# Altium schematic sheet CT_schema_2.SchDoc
size 454 x 387 mm
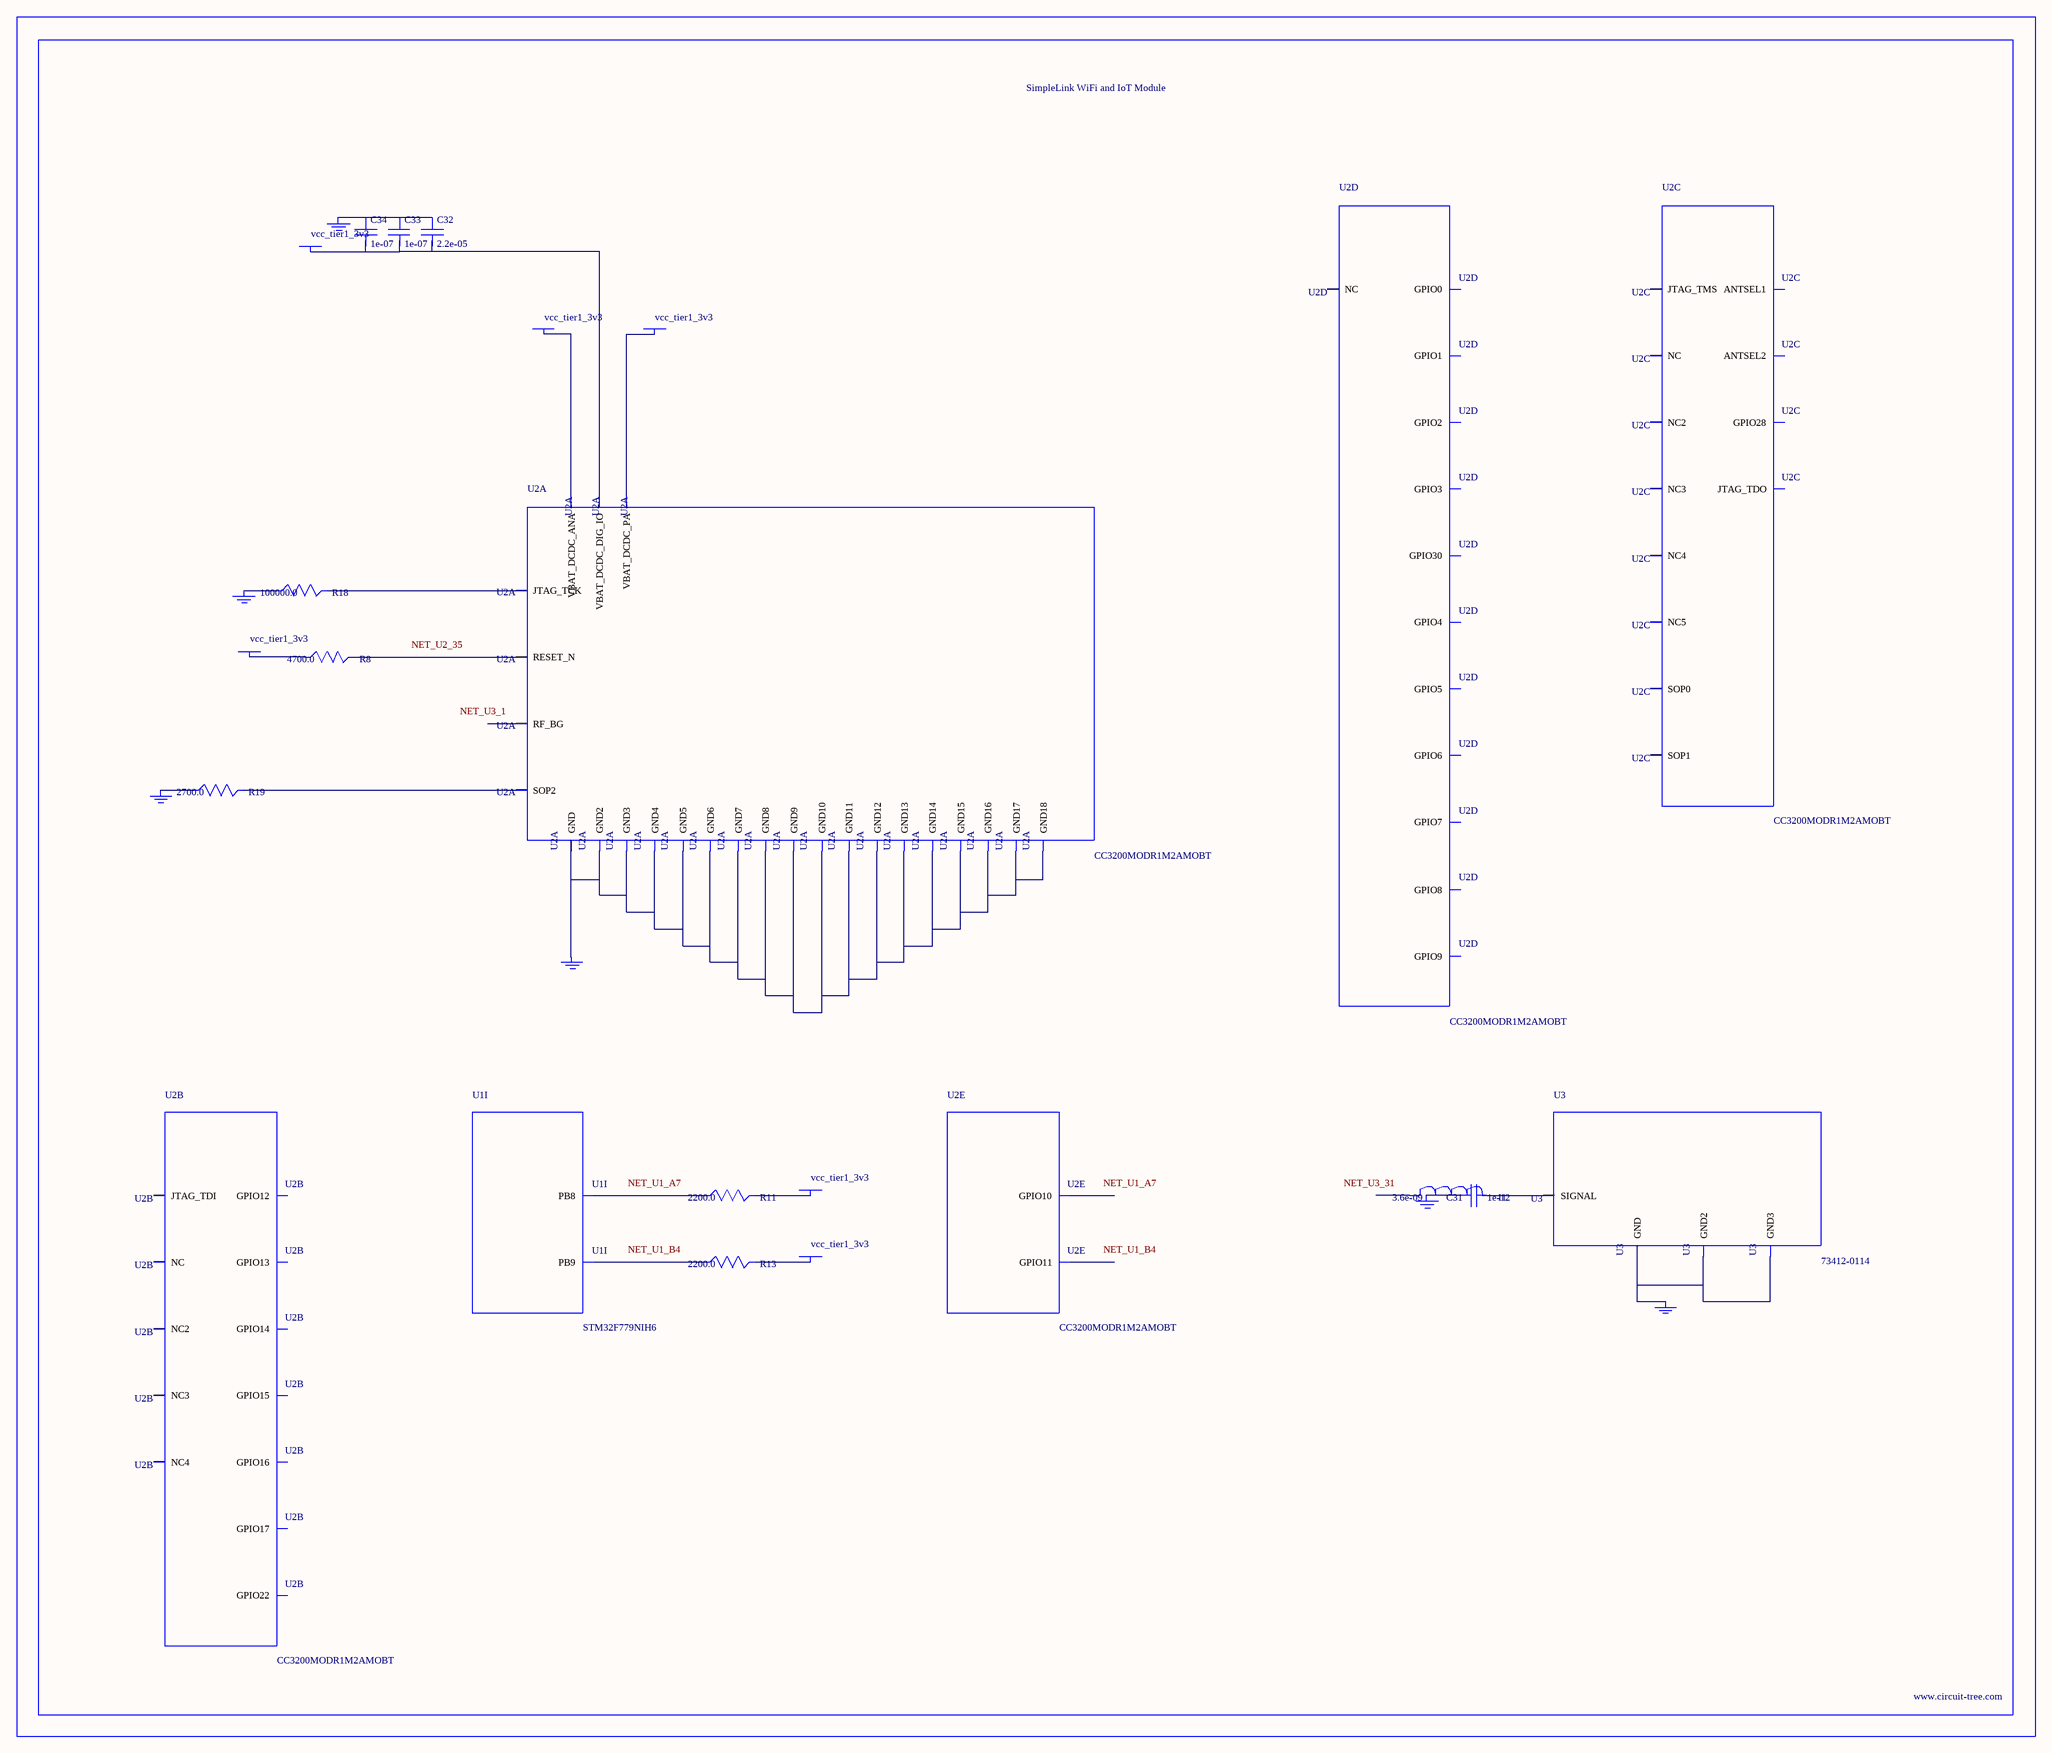
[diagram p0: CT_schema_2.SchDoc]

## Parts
BORDER1  (no value)
C31  1e-12  [C0402]
C32  2.2e-05  [C1210]
C33  1e-07  [C0402]
C34  1e-07  [C0402]
GND_INSTANCE_1_0  (no value)
GND_INSTANCE_1_1  (no value)
GND_INSTANCE_1_2  (no value)
GND_INSTANCE_1_3  (no value)
GND_INSTANCE_1_4  (no value)
GND_INSTANCE_1_5  (no value)
I1  3.6e-09  [C0402]
POWER_INSTANCE_1_0  vcc_tier1_3v3
POWER_INSTANCE_1_1  vcc_tier1_3v3
POWER_INSTANCE_1_2  vcc_tier1_3v3
POWER_INSTANCE_1_3  vcc_tier1_3v3
POWER_INSTANCE_1_4  vcc_tier1_3v3
POWER_INSTANCE_1_5  vcc_tier1_3v3
R8  4700.0  [R0603]
R11  2200.0  [R0603]
R13  2200.0  [R0603]
R18  100000.0  [R0603]
R19  2700.0  [R0603]
U1  STM32F779NIH6  [TFBGA216]  (part I of 16)
U2  CC3200MODR1M2AMOBT  [LGA63S127P16X13_2050X1750X150]  (parts A,B,C,D,E of 5)
U3  73412-0114  [COAXIAL_C]

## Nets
NetC31_1: C31.1 I1.2 U3.1(SIGNAL)
NetC31_2: C31.2 GND_INSTANCE_1_4.0(GND)
NetC32_1: C32.1 C33.1 C34.1 GND_INSTANCE_1_2.0(GND)
NetC32_2: C32.2 C33.2 C34.2 POWER_INSTANCE_1_2.0(PWR) U2.40(VBAT_DCDC_DIG_IO)
NetGND_INSTANCE_1_0_0: GND_INSTANCE_1_0.0(GND) R18.1
NetGND_INSTANCE_1_1_0: GND_INSTANCE_1_1.0(GND) R19.1
NetGND_INSTANCE_1_3_0: GND_INSTANCE_1_3.0(GND) U2.1(GND) U2.2(GND2) U2.16(GND3) U2.27(GND4) U2.28(GND5) U2.30(GND6) U2.32(GND7) U2.38(GND8) U2.43(GND9) U2.55(GND10) U2.56(GND11) U2.57(GND12) U2.58(GND13) U2.59(GND14) U2.60(GND15) U2.61(GND16) U2.62(GND17) U2.63(GND18)
NetGND_INSTANCE_1_5_0: GND_INSTANCE_1_5.0(GND) U3.2(GND) U3.3(GND2) U3.4(GND3)
NetPOWER_INSTANCE_1_0_0: POWER_INSTANCE_1_0.0(PWR) U2.36(VBAT_DCDC_ANA)
NetPOWER_INSTANCE_1_1_0: POWER_INSTANCE_1_1.0(PWR) U2.37(VBAT_DCDC_PA)
NetPOWER_INSTANCE_1_3_0: POWER_INSTANCE_1_3.0(PWR) R8.1
NetPOWER_INSTANCE_1_4_0: POWER_INSTANCE_1_4.0(PWR) R11.2
NetPOWER_INSTANCE_1_5_0: POWER_INSTANCE_1_5.0(PWR) R13.2
NetR8_2: R8.2 U2.35(RESET_N)
NetR11_1: R11.1 U1.A7(PB8)
NetR13_1: R13.1 U1.B4(PB9)
NetR18_2: R18.2 U2.21(JTAG_TCK)
NetR19_2: R19.2 U2.23(SOP2)

Not connected (* = marked no-connect by the designer): I1 1; U2 3(GPIO10) 4(GPIO11) 5(GPIO14) 6(GPIO15) 7(GPIO16) 8(GPIO17) 9(GPIO12) 10(GPIO13) 11(GPIO22) 12(JTAG_TDI) 13(NC) 14(NC2) 15(NC3) 17(NC4) 18(JTAG_TDO) 19(GPIO28) 20(NC) 22(JTAG_TMS) 24(SOP1) 25(ANTSEL1) 26(ANTSEL2) 29(NC2) 31(RF_BG) 33(NC3) 34(SOP0) 39(NC4) 41(NC5) 42(GPIO30) 44(GPIO0) 45(NC) 46(GPIO1) 47(GPIO2) 48(GPIO3) 49(GPIO4) 50(GPIO5) 51(GPIO6) 52(GPIO7) 53(GPIO8) 54(GPIO9)

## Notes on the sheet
- Labels drawn without touching a wire or pin: NET_U1_A7, NET_U1_B4, NET_U2_35, NET_U3_1, NET_U3_31

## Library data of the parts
BORDER1 = BORDER_PAGE1
C31 = C0402C109C3GACTU
C32 = C1210C224K5RACTU
C33 C34 = C0402C104K3RACTU
GND_INSTANCE_1_0-GND_INSTANCE_1_5 = GND
I1 = MCFT0BT3N6
POWER_INSTANCE_1_0-POWER_INSTANCE_1_5 = PWR
R8 = RC0603JR-074K7L
R11 R13 = RC0603JR-072K2L
R18 = RC0603JR-07100KL
R19 = RC0603JR-072K7L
